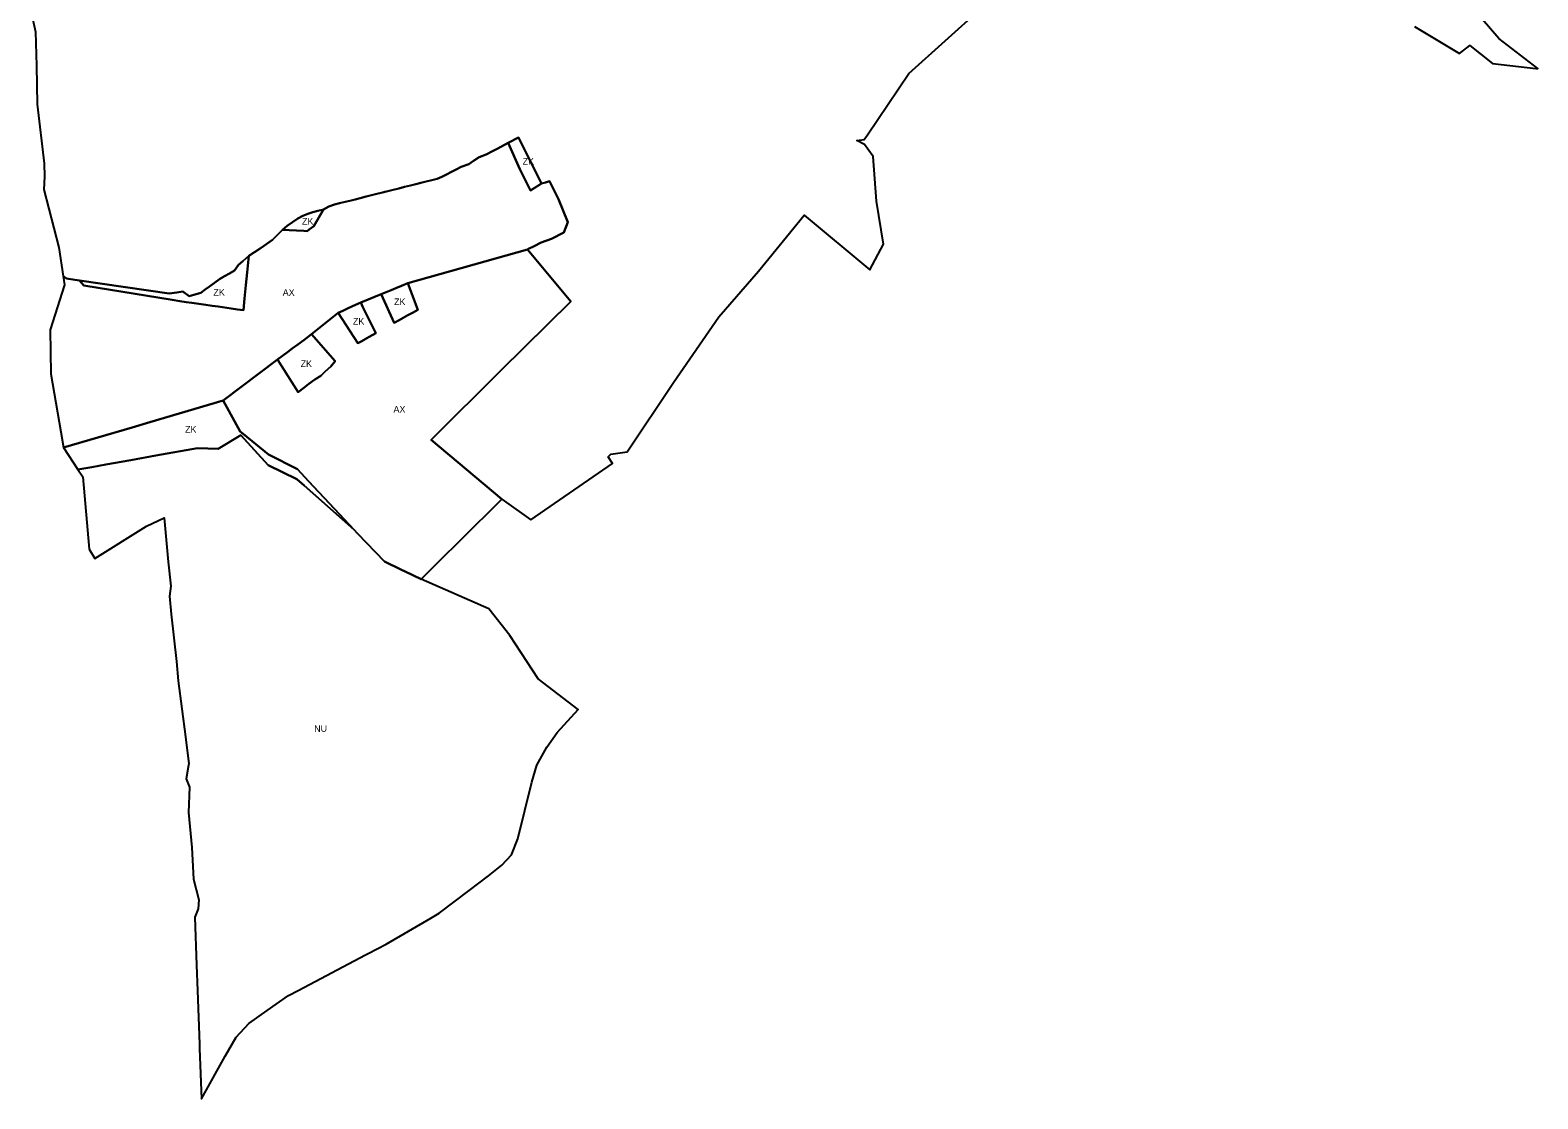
# Model space of a CAD drawing. Extents: x -521939 to -516426, y -1197857 to -1189551.
# Drawn here: x -518685 to -516429, y -1197857 to -1196257 of the extents above; entities that cross this region are included whole.
import ezdxf

# ---------------------------------------------------------------- set-up
doc = ezdxf.new("R2010")
doc.units = 0
for name, color, linetype in [('90710013', 7, 'Continuous'), ('90730013', 7, 'Continuous'), ('90760013', 7, 'Continuous')]:
    doc.layers.add(name, color=color, linetype=linetype)

msp = doc.modelspace()

# ---------------------------------------------------------------- linework, layer by layer
at = {"layer": '90710013'}
for points in [[(-517919.86, -1196486.94), (-517954.36, -1196417.78), (-517969.55, -1196425.83), (-517952.02, -1196465.53), (-517936.18, -1196497.46), (-517919.86, -1196486.94)], [(-518307.33, -1196556.19), (-518297.15, -1196556.7), (-518286.57, -1196557.23), (-518275.51, -1196557.78), (-518270.23, -1196558.04), (-518267.34, -1196555.78), (-518260.49, -1196550.42), (-518251.05, -1196534.28), (-518245.9, -1196525.46), (-518254.46, -1196527.76), (-518262.11, -1196529.82), (-518269.54, -1196532.4), (-518277.1, -1196535.02), (-518284.36, -1196539.13), (-518292.48, -1196544.8), (-518300.32, -1196550.26), (-518307.33, -1196556.19)], [(-518611.13, -1196631.81), (-518604.77, -1196639.32), (-518472.61, -1196661.14), (-518461.08, -1196662.79), (-518451.52, -1196664.16), (-518443.06, -1196665.37), (-518422.2, -1196668.36), (-518412.63, -1196669.73), (-518403.42, -1196671.05), (-518384.01, -1196673.82), (-518374.74, -1196675.15), (-518365.83, -1196676.42), (-518364.1, -1196659.07), (-518362.08, -1196638.75), (-518360.19, -1196619.78), (-518357.75, -1196595.26), (-518366.72, -1196602.92), (-518373.35, -1196608.57), (-518379.16, -1196617.04), (-518386.73, -1196621.41), (-518394.14, -1196625.69), (-518401.77, -1196630.1), (-518416.41, -1196640.72), (-518423.07, -1196645.55), (-518429.46, -1196650.18), (-518447.12, -1196655.27), (-518456.43, -1196648.49), (-518465.38, -1196649.88), (-518476.74, -1196651.64), (-518611.13, -1196631.81)], [(-518119.98, -1196636.04), (-518129.43, -1196640.01), (-518137.54, -1196643.41), (-518144.97, -1196646.52), (-518152.37, -1196649.62), (-518159.52, -1196652.61), (-518140.08, -1196695.39), (-518132.79, -1196691.31), (-518126.73, -1196687.92), (-518119.72, -1196683.99), (-518112.86, -1196680.15), (-518104.99, -1196675.74), (-518119.98, -1196636.04)], [(-518223.82, -1196680.26), (-518194.72, -1196725.98), (-518188.63, -1196722.57), (-518181.28, -1196718.46), (-518177.71, -1196716.46), (-518167.87, -1196710.95), (-518187.24, -1196671.76), (-518190.02, -1196664.74), (-518202.61, -1196670.52), (-518210.25, -1196674.03), (-518217.01, -1196677.13), (-518223.82, -1196680.26)], [(-518314.62, -1196750.17), (-518283.76, -1196798.87), (-518275.61, -1196792.4), (-518268.19, -1196786.5), (-518258.73, -1196780.27), (-518249.81, -1196774.4), (-518243.27, -1196768.33), (-518234.82, -1196760.49), (-518228.44, -1196752.68), (-518263.83, -1196712.28), (-518275.64, -1196721.09), (-518284.28, -1196727.54), (-518292.91, -1196733.98), (-518299.96, -1196739.24), (-518307.47, -1196744.84), (-518314.62, -1196750.17)], [(-518613.42, -1196914.98), (-518592.65, -1196911.12), (-518571.88, -1196907.25), (-518534.47, -1196900.69), (-518497.06, -1196894.12), (-518434.72, -1196882.88), (-518419.2, -1196883.38), (-518403.69, -1196883.88), (-518369.69, -1196863.69), (-518328.64, -1196908.57), (-518285.89, -1196929.32), (-518275.03, -1196938.94), (-518200.83, -1197004.68), (-518229.79, -1196973.69), (-518268.42, -1196932.35), (-518285.15, -1196914.46), (-518328.32, -1196892.23), (-518366.35, -1196861.67), (-518370.59, -1196857.92), (-518395.91, -1196811.65), (-518505.67, -1196843.94), (-518532.46, -1196851.82), (-518635.06, -1196882), (-518613.42, -1196914.98)]]:
    msp.add_lwpolyline(points, dxfattribs=at)
at = {"layer": '90730013'}
for points in [[(-518684.91, -1196223.86), (-518676.71, -1196259.65), (-518675.49, -1196310.93), (-518674.27, -1196368.11), (-518664.07, -1196456.63), (-518663.46, -1196476.54), (-518664.51, -1196495.66), (-518642.14, -1196582.69), (-518635.54, -1196625.44), (-518630.52, -1196628.95), (-518618.09, -1196630.78), (-518611.13, -1196631.81)], [(-518611.13, -1196631.81), (-518476.74, -1196651.64), (-518465.38, -1196649.88), (-518456.43, -1196648.49), (-518447.12, -1196655.27), (-518429.46, -1196650.18), (-518423.07, -1196645.55), (-518416.41, -1196640.72), (-518401.77, -1196630.1), (-518394.14, -1196625.69), (-518386.73, -1196621.41), (-518379.16, -1196617.04), (-518373.35, -1196608.57), (-518366.72, -1196602.92), (-518357.75, -1196595.26), (-518349.43, -1196589.65), (-518340.85, -1196583.87), (-518322.2, -1196571.31), (-518314.78, -1196563.76), (-518307.33, -1196556.19), (-518300.32, -1196550.26), (-518292.48, -1196544.8), (-518284.36, -1196539.13), (-518277.1, -1196535.02), (-518269.54, -1196532.4), (-518262.11, -1196529.82), (-518254.46, -1196527.76), (-518245.9, -1196525.46), (-518238.04, -1196521.23), (-518229.46, -1196518.32), (-518221.9, -1196516.42), (-518213.61, -1196514.33), (-518206.43, -1196512.52), (-518198.74, -1196510.58), (-518191.03, -1196508.64), (-518181.93, -1196506.35), (-518170.37, -1196503.44), (-518155.76, -1196499.77), (-518154.48, -1196499.45), (-518151.95, -1196498.81), (-518143.67, -1196496.73), (-518133.19, -1196494.09), (-518124.71, -1196491.96), (-518115.65, -1196489.68), (-518107.77, -1196487.7), (-518100.17, -1196485.79), (-518092.19, -1196483.78), (-518083.93, -1196481.7), (-518076.13, -1196479.73), (-518069.11, -1196476.93), (-518061.97, -1196473.23), (-518054.71, -1196469.46), (-518047.76, -1196465.86), (-518040.21, -1196461.94), (-518028.81, -1196457.86), (-518021.44, -1196452.97), (-518012.91, -1196447.31), (-518002.79, -1196443.46), (-517993.14, -1196438.34), (-517985.3, -1196434.18), (-517969.55, -1196425.83), (-517954.36, -1196417.78), (-517919.86, -1196486.94), (-517913.75, -1196485.06), (-517907.64, -1196483.18), (-517894.63, -1196510.06), (-517880.68, -1196544.48), (-517886.45, -1196560.09), (-517905.03, -1196569.49), (-517920.51, -1196575.3), (-517930.62, -1196580.45), (-517939.19, -1196584.82), (-517940.75, -1196585.61), (-517876.11, -1196663.33), (-517980.47, -1196766.88), (-518084.82, -1196870.43), (-517979.14, -1196959.07), (-517935.92, -1196989.92), (-517813.49, -1196905.82), (-517820.25, -1196896.05), (-517816.14, -1196891.68), (-517791.47, -1196888.16), (-517722.2, -1196784.68), (-517654.47, -1196686.28), (-517595.12, -1196618.05), (-517526.62, -1196534.15), (-517428.45, -1196615.95), (-517408.15, -1196577.68), (-517418.45, -1196513), (-517423.61, -1196446.17), (-517436.75, -1196428.36), (-517447.83, -1196422.29), (-517436.97, -1196421.1), (-517432.16, -1196413.99), (-517370.19, -1196322.31), (-517261.71, -1196224.29)], [(-516613.68, -1196251.89), (-516546.39, -1196292.1), (-516530.76, -1196280.17), (-516496.78, -1196306.95), (-516432.19, -1196314.48), (-516429.12, -1196314.84), (-516487.35, -1196269.61), (-516512.28, -1196241)], [(-518613.42, -1196914.98), (-518606.26, -1196925.9), (-518596.53, -1197033.9), (-518588, -1197047.91), (-518510.74, -1196999.5), (-518484.35, -1196987.06), (-518478.28, -1197052.83), (-518474.25, -1197089.5), (-518476.45, -1197104.51), (-518473.78, -1197131.38), (-518465.73, -1197202.12), (-518463.39, -1197230.92), (-518452.59, -1197315), (-518447.43, -1197355.16), (-518447.84, -1197357.46), (-518451.47, -1197377.61), (-518446.52, -1197390.37), (-518448.18, -1197428.02), (-518443.09, -1197480.72), (-518440.71, -1197527.7), (-518432.6, -1197558.64), (-518433.44, -1197572.46), (-518438.56, -1197584.67), (-518435.95, -1197656.89), (-518434.59, -1197694.65), (-518431.69, -1197774.8), (-518431.46, -1197781.26), (-518428.74, -1197856.73), (-518393.29, -1197793.04), (-518376.86, -1197764.28), (-518357.94, -1197743.84), (-518330.37, -1197724.4), (-518298.17, -1197701.87), (-518283.9, -1197694.34), (-518183.14, -1197641.17), (-518179.17, -1197639.1), (-518152.49, -1197625.15), (-518085.41, -1197586.07), (-518073.1, -1197578.9), (-518027.99, -1197544.71), (-517999.07, -1197522.78), (-517979.06, -1197506.74), (-517964.82, -1197491.32), (-517955.22, -1197467.73), (-517934.54, -1197382.65), (-517926.9, -1197357.23), (-517912, -1197330.37), (-517896.55, -1197308.23), (-517865.19, -1197274.24), (-517924.91, -1197228.36), (-517967.31, -1197163.24), (-517998.84, -1197123.4), (-518099.9, -1197079.1), (-518123.76, -1197067.57), (-518129.22, -1197064.94), (-518154.91, -1197052.53), (-518195.2, -1197010.55), (-518200.83, -1197004.68), (-518275.03, -1196938.94), (-518285.89, -1196929.32), (-518328.64, -1196908.57), (-518369.69, -1196863.69), (-518403.69, -1196883.88), (-518419.2, -1196883.38), (-518434.72, -1196882.88), (-518497.06, -1196894.12), (-518534.47, -1196900.69), (-518571.88, -1196907.25), (-518592.65, -1196911.12), (-518613.42, -1196914.98)]]:
    msp.add_lwpolyline(points, dxfattribs=at)
at = {"layer": '90760013'}
for points in [[(-518611.13, -1196631.81), (-518618.09, -1196630.78), (-518630.52, -1196628.95), (-518635.54, -1196625.44), (-518633.55, -1196638.3), (-518655.02, -1196705.87), (-518654.2, -1196771.74), (-518639.16, -1196858.36), (-518635.06, -1196882), (-518532.46, -1196851.82), (-518505.67, -1196843.94), (-518395.91, -1196811.65), (-518314.62, -1196750.17), (-518307.47, -1196744.84), (-518299.96, -1196739.24), (-518292.91, -1196733.98), (-518284.28, -1196727.54), (-518275.64, -1196721.09), (-518263.83, -1196712.28), (-518223.82, -1196680.26), (-518217.01, -1196677.13), (-518210.25, -1196674.03), (-518202.61, -1196670.52), (-518190.02, -1196664.74), (-518159.52, -1196652.61), (-518152.37, -1196649.62), (-518144.97, -1196646.52), (-518137.54, -1196643.41), (-518129.43, -1196640.01), (-518119.98, -1196636.04), (-517940.75, -1196585.61), (-517939.19, -1196584.82), (-517930.62, -1196580.45), (-517920.51, -1196575.3), (-517905.03, -1196569.49), (-517886.45, -1196560.09), (-517880.68, -1196544.48), (-517894.63, -1196510.06), (-517907.64, -1196483.18), (-517913.75, -1196485.06), (-517919.86, -1196486.94), (-517936.18, -1196497.46), (-517952.02, -1196465.53), (-517969.55, -1196425.83), (-517985.3, -1196434.18), (-517993.14, -1196438.34), (-518002.79, -1196443.46), (-518012.91, -1196447.31), (-518021.44, -1196452.97), (-518028.81, -1196457.86), (-518040.21, -1196461.94), (-518047.76, -1196465.86), (-518054.71, -1196469.46), (-518061.97, -1196473.23), (-518069.11, -1196476.93), (-518076.13, -1196479.73), (-518083.93, -1196481.7), (-518092.19, -1196483.78), (-518100.17, -1196485.79), (-518107.77, -1196487.7), (-518115.65, -1196489.68), (-518124.71, -1196491.96), (-518133.19, -1196494.09), (-518143.67, -1196496.73), (-518151.95, -1196498.81), (-518154.48, -1196499.45), (-518155.76, -1196499.77), (-518170.37, -1196503.44), (-518181.93, -1196506.35), (-518191.03, -1196508.64), (-518198.74, -1196510.58), (-518206.43, -1196512.52), (-518213.61, -1196514.33), (-518221.9, -1196516.42), (-518229.46, -1196518.32), (-518238.04, -1196521.23), (-518245.9, -1196525.46), (-518251.05, -1196534.28), (-518260.49, -1196550.42), (-518267.34, -1196555.78), (-518270.23, -1196558.04), (-518275.51, -1196557.78), (-518286.57, -1196557.23), (-518297.15, -1196556.7), (-518307.33, -1196556.19), (-518314.78, -1196563.76), (-518322.2, -1196571.31), (-518340.85, -1196583.87), (-518349.43, -1196589.65), (-518357.75, -1196595.26), (-518360.19, -1196619.78), (-518362.08, -1196638.75), (-518364.1, -1196659.07), (-518365.83, -1196676.42), (-518374.74, -1196675.15), (-518384.01, -1196673.82), (-518403.42, -1196671.05), (-518412.63, -1196669.73), (-518422.2, -1196668.36), (-518443.06, -1196665.37), (-518451.52, -1196664.16), (-518461.08, -1196662.79), (-518472.61, -1196661.14), (-518604.77, -1196639.32), (-518611.13, -1196631.81)], [(-518314.62, -1196750.17), (-518395.91, -1196811.65), (-518370.59, -1196857.92), (-518366.35, -1196861.67), (-518328.32, -1196892.23), (-518285.15, -1196914.46), (-518268.42, -1196932.35), (-518229.79, -1196973.69), (-518200.83, -1197004.68), (-518195.2, -1197010.55), (-518154.91, -1197052.53), (-518129.22, -1197064.94), (-518123.76, -1197067.57), (-518099.9, -1197079.1), (-518012.54, -1196992.27), (-518007.29, -1196987.05), (-517981.57, -1196961.49), (-517979.14, -1196959.07), (-518084.82, -1196870.43), (-517980.47, -1196766.88), (-517876.11, -1196663.33), (-517940.75, -1196585.61), (-518119.98, -1196636.04), (-518104.99, -1196675.74), (-518112.86, -1196680.15), (-518119.72, -1196683.99), (-518126.73, -1196687.92), (-518132.79, -1196691.31), (-518140.08, -1196695.39), (-518159.52, -1196652.61), (-518190.02, -1196664.74), (-518187.24, -1196671.76), (-518167.87, -1196710.95), (-518177.71, -1196716.46), (-518181.28, -1196718.46), (-518188.63, -1196722.57), (-518194.72, -1196725.98), (-518223.82, -1196680.26), (-518263.83, -1196712.28), (-518228.44, -1196752.68), (-518234.82, -1196760.49), (-518243.27, -1196768.33), (-518249.81, -1196774.4), (-518258.73, -1196780.27), (-518268.19, -1196786.5), (-518275.61, -1196792.4), (-518283.76, -1196798.87), (-518314.62, -1196750.17)]]:
    msp.add_lwpolyline(points, dxfattribs=at)

# ---------------------------------------------------------------- texts
at = {"layer": '90710013'}
for rotation, p in [(0, (-517948.04, -1196458.59)), (360, (-518278.18, -1196548.3)), (360, (-518410.81, -1196654.58)), (360, (-518140.45, -1196668.81)), (360, (-518202.01, -1196698.02)), (0, (-518280.29, -1196761.54)), (360, (-518453.22, -1196859.8))]:
    msp.add_text('ZK', height=10, rotation=rotation, dxfattribs=at).set_placement(p)
at = {"layer": '90730013'}
msp.add_text('NU', height=10, rotation=360, dxfattribs=at).set_placement((-518260.02, -1197307.53))
at = {"layer": '90760013'}
for p in [(-518307.08, -1196654.95), (-518141.31, -1196829.75)]:
    msp.add_text('AX', height=10, rotation=360, dxfattribs=at).set_placement(p)

doc.saveas('drawing.dxf')
